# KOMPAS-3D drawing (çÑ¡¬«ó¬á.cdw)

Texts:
  ТМ 016.01.04.000СБ
  Зенковка @2~25
  Текст на чертеже
  Размерные надписи
  Шероховатость
  Линия-выноска #1
  Линия-выноска #2
  Линия-выноска #3
  Отклонения формы и база
  Заголовок таблицы
  Ячейка таблицы
  Стрелка вида
  Обозначение изменения
  Фигурная скобка
  Номер узла
  Марка координационной оси
  VRCB
  Выносная надпись
  Обозначение узла
  Марка/позиционное обозначение с линией-выноской
  Марка/позиционное обозначение на линии
  Марка/позиционное обозначение без линии-выноски
  1.  Материал фрезы Р6М5  64...67HRC
  2. Материал хвостовика Сталь45 - 37...42HRC
  Зенковка  25
  Детали
  Фреза
  Хвостовик
  Штифт
  Винт
  ТМ 016.01.04.000СБ-
Dimensions and other numbers on the sheet: 7; 102; 1,5; 1; 2; 3; 4; 25; 13; 1:1; 0; 5; 6; 8; 9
